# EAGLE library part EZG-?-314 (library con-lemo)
LEMO Connector Source: http://www.lemo.com/pdfs/catalog/ROW/German/unipole_multipole.pdf
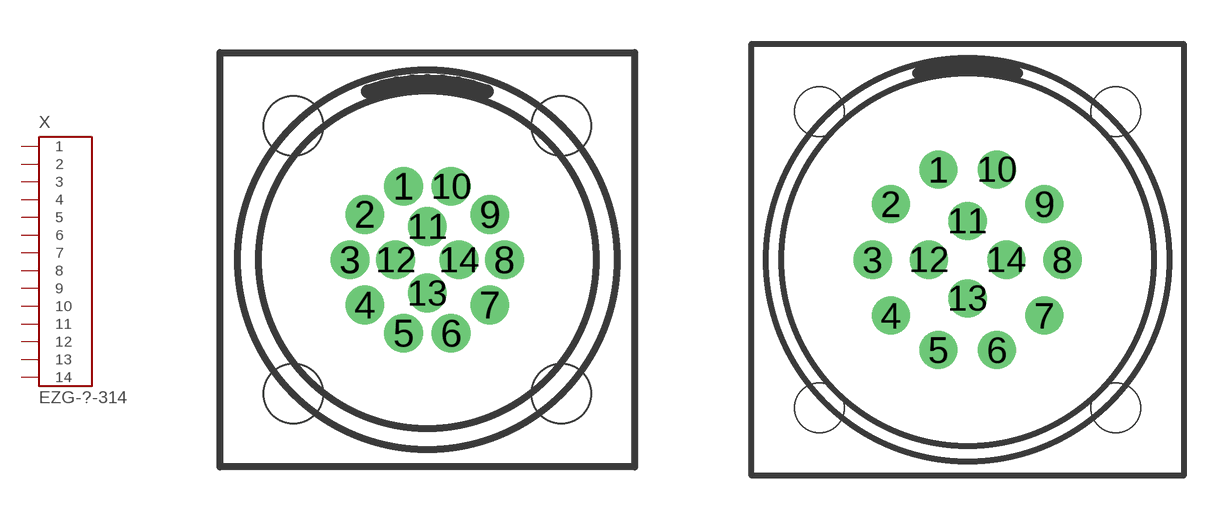
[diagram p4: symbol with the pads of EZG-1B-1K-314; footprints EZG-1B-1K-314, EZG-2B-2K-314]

Designator prefix X

## EZG-1B-314 (OC_FARNELL: unknown; OC_NEWARK: unknown)  [EZG-1B-1K-314]
1  1  pas
2  2  pas
3  3  pas
4  4  pas
5  5  pas
6  6  pas
7  7  pas
8  8  pas
9  9  pas
10  10  pas
11  11  pas
12  12  pas
13  13  pas
14  14  pas

## EZG-1K-314 (OC_FARNELL: unknown; OC_NEWARK: unknown)  [EZG-1B-1K-314]
Pads as for EZG-1B-1K-314

## EZG-2B-314 (OC_FARNELL: unknown; OC_NEWARK: unknown)  [EZG-2B-2K-314]
Pads as for EZG-1B-1K-314

## EZG-2K-314 (OC_FARNELL: unknown; OC_NEWARK: unknown)  [EZG-2B-2K-314]
Pads as for EZG-1B-1K-314

## Footprint EZG-1B-1K-314 (pad centres in mm)
LEMO Connector Source: http://www.lemo.com/pdfs/catalog/ROW/German/unipole_multipole.pdf
drill 0.6 pad 1 round: 1 -0.68,2.092; 2 -1.78,1.293; 3 -2.2,0; 4 -1.78,-1.293; 5 -0.68,-2.092; 6 0.68,-2.092; 7 1.78,-1.293; 8 2.2,0; 9 1.78,1.293; 10 0.68,2.092; 11 0,0.95; 12 -0.9,0; 13 0,-0.95; 14 0.9,0
hole 1.7 at -3.81,3.81
hole 1.7 at 3.81,3.81
hole 1.7 at 3.81,-3.81
hole 1.7 at -3.81,-3.81

## Footprint EZG-2B-2K-314 (pad centres in mm)
LEMO Connector Source: http://www.lemo.com/pdfs/catalog/ROW/German/unipole_multipole.pdf
drill 0.8 pad 1.3 round: 1 -1.004,3.091; 2 -2.629,1.91; 3 -3.25,0; 4 -2.629,-1.91; 5 -1.004,-3.091; 6 1.004,-3.091; 7 2.629,-1.91; 8 3.25,0; 9 2.629,1.91; 10 1.004,3.091; 11 0,1.325; 12 -1.325,0; 13 0,-1.325; 14 1.325,0
hole 1.7 at -5.08,5.08
hole 1.7 at 5.08,5.08
hole 1.7 at 5.08,-5.08
hole 1.7 at -5.08,-5.08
